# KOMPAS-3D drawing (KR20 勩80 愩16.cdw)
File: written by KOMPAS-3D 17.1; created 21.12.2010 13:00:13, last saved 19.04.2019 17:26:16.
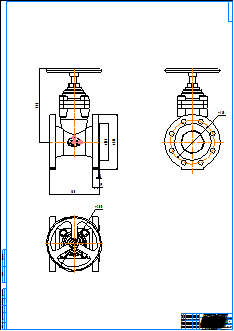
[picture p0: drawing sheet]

Title block, sheet 1: name: KR20 Ду80 Ру16; material: Внимание! Данный продукт является объектом авторского права ООО «Торговый Дом АДЛ». / Запрещается изменение, копирование, распространение / (в том числе путем копирования на другие сайты и ресурсы в Интернете) / или любое иное использование информации и объектов без предварительного / согласия правообладателя (ООО «Торговый Дом АДЛ»).; scale: 1:1; sheets: 1; organisation: ООО "Торговый дом АДЛ"; sheet format: A0; stored path: \\adlc.lan\data\АДЛ_ПКД\3D-модели\ADL production\Клиновые задвижки серии KR ГРАНАР\Клиновые задвижки KR20\KOMPAS 2D\KR20 Ду80 Ру16.cdw

Views: Спереди 1, Проекционный вид 2, Проекционный вид 3
Dimensions and other numbers on the sheet: 133; 200; 3; 19; 180; 160; 264; 1:1; 1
